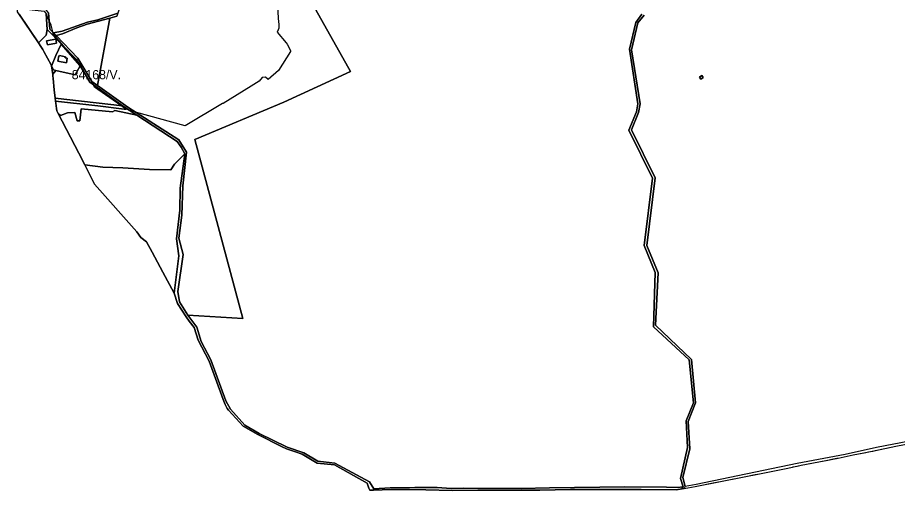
# Model space of a CAD drawing. Extents: x -477304 to -465429, y -1159113 to -1149210.
# Drawn here: x -472687 to -471252, y -1159113 to -1158342 of the extents above; entities that cross this region are included whole.
import ezdxf

# ---------------------------------------------------------------- set-up
doc = ezdxf.new("R2010")
doc.units = 0
for name, color, linetype in [('BPEJ_s', 7, 'Continuous'), ('ostatni_s', 7, 'Continuous'), ('PUPFL_s', 7, 'Continuous'), ('trav_porost_s', 7, 'Continuous')]:
    doc.layers.add(name, color=color, linetype=linetype)

msp = doc.modelspace()

# ---------------------------------------------------------------- linework, layer by layer
at = {"layer": 'BPEJ_s'}
msp.add_line((-472106.49, -1159112.88), (-472078.21, -1159112.05), dxfattribs=at)
for points in [[(-472265.73, -1158263.74), (-472261.91, -1158343.47), (-472260.85, -1158353.65), (-472260.85, -1158359.59), (-472262.02, -1158362.28), (-472263.61, -1158365.95), (-472248.55, -1158383.34), (-472247.32, -1158385.73), (-472241.98, -1158396.06), (-472241.98, -1158397.75), (-472261.06, -1158428.5), (-472278.24, -1158443.34), (-472282.69, -1158439.31), (-472287.99, -1158439.74), (-472292.66, -1158445.89), (-472305.8, -1158454.16), (-472351.6, -1158482.57), (-472352.45, -1158482.57), (-472413.61, -1158518.57), (-472494.46, -1158496.29), (-472500, -1158494.76), (-472504.44, -1158493.37), (-472510.2, -1158491.57), (-472518.4, -1158485.77), (-472561.24, -1158455.52), (-472563.55, -1158451.26), (-472571.49, -1158436.66), (-472576.43, -1158427.57), (-472578, -1158425.91), (-472588.26, -1158415.03), (-472600.95, -1158401.58), (-472612.08, -1158388.5), (-472628.9, -1158368.73), (-472629.67, -1158365.51), (-472632.33, -1158354.51), (-472635.42, -1158347.42), (-472640.28, -1158336.28)], [(-472265.73, -1158263.74), (-472261.91, -1158343.47), (-472260.85, -1158353.65), (-472260.85, -1158359.59), (-472262.02, -1158362.28), (-472263.61, -1158365.95), (-472248.55, -1158383.34), (-472247.32, -1158385.73), (-472241.98, -1158396.06), (-472241.98, -1158397.75), (-472261.06, -1158428.5), (-472278.24, -1158443.34), (-472282.69, -1158439.31), (-472287.99, -1158439.74), (-472292.66, -1158445.89), (-472305.8, -1158454.16), (-472351.6, -1158482.57), (-472352.45, -1158482.57), (-472413.61, -1158518.57), (-472494.46, -1158496.29), (-472500, -1158494.76), (-472504.44, -1158493.37), (-472510.2, -1158491.57), (-472513.19, -1158491.31), (-472555.96, -1158486.36), (-472624.87, -1158478.39), (-472624.88, -1158478.39), (-472622.97, -1158494.2), (-472620.8, -1158498.39), (-472587.24, -1158563.25), (-472577.32, -1158582.48), (-472561.25, -1158613.94), (-472492.21, -1158691.54), (-472485.63, -1158700.62), (-472476.75, -1158708.09), (-472467.3, -1158724.65), (-472450.08, -1158757.54), (-472431.32, -1158791.54), (-472426.3, -1158808.3), (-472411.66, -1158830.16), (-472406.77, -1158837.27), (-472398.9, -1158847.76), (-472392.31, -1158868.11), (-472374.4, -1158902.5), (-472351.69, -1158965.36)], [(-472684.26, -1158336.59), (-472652.61, -1158383.21), (-472648.83, -1158389.61), (-472646.9, -1158392.88), (-472645.98, -1158394.44), (-472644.14, -1158397.55), (-472632.14, -1158419.49), (-472631.64, -1158421.66), (-472631.1, -1158424.05), (-472630.04, -1158431.55), (-472629.64, -1158434.37), (-472629.25, -1158437.13), (-472628.6, -1158441.68), (-472627.33, -1158460.07), (-472625.47, -1158473.45), (-472624.88, -1158478.39), (-472624.87, -1158478.39), (-472555.96, -1158486.36), (-472513.19, -1158491.31), (-472510.2, -1158491.57), (-472518.4, -1158485.77), (-472561.24, -1158455.52), (-472563.55, -1158451.26), (-472571.49, -1158436.66), (-472576.43, -1158427.57), (-472578, -1158425.91), (-472588.26, -1158415.03), (-472600.95, -1158401.58), (-472612.08, -1158388.5), (-472628.9, -1158368.73), (-472629.67, -1158365.51), (-472632.33, -1158354.51), (-472635.42, -1158347.42), (-472640.28, -1158336.28)], [(-472351.69, -1158965.36), (-472348.41, -1158973.33), (-472345.03, -1158979.57), (-472342.98, -1158982.7), (-472319.03, -1159008.67), (-472295.2, -1159022.38), (-472255.57, -1159042.54), (-472248.04, -1159045.76), (-472234.94, -1159050.02), (-472222.67, -1159054.37), (-472198.26, -1159068.75), (-472170.01, -1159071.87), (-472116.62, -1159101.37), (-472114.01, -1159109.72), (-472112.58, -1159113.06), (-472106.49, -1159112.88)], [(-472078.21, -1159112.05), (-472047.81, -1159112.11), (-472021.14, -1159112.52), (-471977.91, -1159113.35), (-471936.22, -1159113.01), (-471890.93, -1159113.19), (-471834.93, -1159112.74), (-471785, -1159112.1), (-471763.77, -1159111.82), (-471752.7, -1159111.68), (-471734.12, -1159111.7), (-471689.5, -1159111.75), (-471689.33, -1159111.75), (-471689.22, -1159111.75), (-471688.14, -1159111.75), (-471685.96, -1159111.75), (-471680.14, -1159111.76), (-471669.78, -1159111.77), (-471669.68, -1159111.77), (-471660.21, -1159111.85), (-471645.72, -1159111.98), (-471611.89, -1159112.28), (-471603.14, -1159110.69), (-471602.61, -1159110.59), (-471599.77, -1159110.08), (-471599.35, -1159110), (-471581.37, -1159106.81), (-471549.7, -1159100.71), (-471543.64, -1159099.54), (-471540.41, -1159098.92), (-471493.61, -1159089.57), (-471489.04, -1159088.65), (-471484.02, -1159087.65), (-471476.57, -1159086.16), (-471474.07, -1159085.66), (-471433.45, -1159077.57), (-471422.79, -1159075.31), (-471421.78, -1159075.09), (-471415.52, -1159073.76), (-471408.77, -1159072.33), (-471371.33, -1159065.04), (-471367.83, -1159064.36), (-471365.45, -1159063.9), (-471358.66, -1159062.58), (-471350.7, -1159061.03), (-471348.39, -1159060.58), (-471323.83, -1159055.59), (-471306.74, -1159052.12), (-471305.92, -1159051.96), (-471299.03, -1159050.54), (-471292.08, -1159049.11), (-471287.45, -1159048.16), (-471254.45, -1159041.38), (-471240.01, -1159038.58)]]:
    msp.add_lwpolyline(points, dxfattribs=at)
at = {"layer": 'ostatni_s'}
for points in [[(-472636.66, -1158334.41), (-472634.14, -1158360.85), (-472628.35, -1158366.89), (-472623.97, -1158371.45), (-472588.71, -1158408.22), (-472565.63, -1158446.34), (-472556.65, -1158452.72), (-472506.92, -1158488.31), (-472423.92, -1158541.46), (-472411.56, -1158561.7), (-472417.57, -1158616.75), (-472418.95, -1158664.4), (-472423.83, -1158702.03), (-472417.07, -1158728.53), (-472425.73, -1158788.91), (-472422.84, -1158805.67), (-472408.96, -1158827.72), (-472394.58, -1158847.34), (-472387.53, -1158870.46), (-472371.56, -1158900.29), (-472347.13, -1158967.52), (-472339.75, -1158981), (-472316.38, -1159007.05), (-472293.04, -1159020.55), (-472247.08, -1159042.83), (-472220.16, -1159052.18), (-472197.25, -1159065.9), (-472169.29, -1159069.07), (-472112.77, -1159099.12), (-472105.93, -1159110.54), (-472106.49, -1159112.88), (-472112.58, -1159113.06), (-472114.01, -1159109.72), (-472116.62, -1159101.37), (-472170.01, -1159071.87), (-472198.26, -1159068.75), (-472222.67, -1159054.37), (-472234.94, -1159050.02), (-472248.04, -1159045.76), (-472255.57, -1159042.54), (-472295.2, -1159022.38), (-472319.03, -1159008.67), (-472342.98, -1158982.7), (-472345.03, -1158979.57), (-472348.41, -1158973.33), (-472351.69, -1158965.36), (-472374.4, -1158902.5), (-472392.31, -1158868.11), (-472398.9, -1158847.76), (-472406.77, -1158837.27), (-472411.66, -1158830.16), (-472426.3, -1158808.3), (-472431.32, -1158791.54), (-472423.99, -1158730.94), (-472427.41, -1158702.9), (-472422.13, -1158656.11), (-472421.5, -1158620.63), (-472414.06, -1158564.21), (-472420.02, -1158553.6), (-472426.34, -1158544.46), (-472492.55, -1158501.15), (-472515.55, -1158486.1), (-472568.9, -1158447.38), (-472584.99, -1158420.74), (-472591.13, -1158410.03), (-472638.44, -1158361.41), (-472640.4, -1158335.93)], [(-471664.69, -1158338.46), (-471674.96, -1158350.8), (-471685.46, -1158394.82), (-471671.6, -1158482.85), (-471674, -1158497.16), (-471685.4, -1158525.11), (-471646.64, -1158603.72), (-471660.68, -1158713.93), (-471642.02, -1158758.33), (-471646.5, -1158844.06), (-471587.57, -1158899.63), (-471581.07, -1158970.7), (-471592.91, -1159000.77), (-471590.23, -1159045.68), (-471601.85, -1159092.38), (-471597.73, -1159106.93), (-471599.35, -1159110), (-471599.77, -1159110.08), (-471603.14, -1159110.69), (-471601.46, -1159107.66), (-471605.7, -1159094.13), (-471594.34, -1159043.47), (-471596.58, -1158999.97), (-471584.35, -1158970.72), (-471591.37, -1158900.67), (-471649.86, -1158846.71), (-471646.64, -1158757.71), (-471664.56, -1158713.76), (-471651.3, -1158604.1), (-471689.68, -1158525.87), (-471677.39, -1158495.91), (-471675.29, -1158482.93), (-471688.96, -1158393.86), (-471678.55, -1158349.99), (-471668.72, -1158336.66)]]:
    msp.add_lwpolyline(points, dxfattribs=at)
for points in [[(-472573.2, -1158353.08), (-472590.17, -1158359.02), (-472613.81, -1158368.63), (-472623.97, -1158371.45), (-472628.35, -1158366.89), (-472614.22, -1158364.11), (-472572.65, -1158349.62), (-472555.93, -1158345.78), (-472523.33, -1158335.05), (-472524.97, -1158339.98), (-472536.51, -1158343.14)], [(-472638.44, -1158361.41), (-472591.13, -1158410.03), (-472584.99, -1158420.74), (-472615.9, -1158385.42), (-472624.62, -1158404.27), (-472631.64, -1158421.66), (-472632.14, -1158419.49), (-472644.14, -1158397.55), (-472645.98, -1158394.44), (-472646.9, -1158392.88), (-472648.83, -1158389.61), (-472652.61, -1158383.21), (-472640.26, -1158370.82)], [(-472639.52, -1158380.11), (-472624.5, -1158377.44), (-472623.3, -1158384.2), (-472638.31, -1158386.88)], [(-472624.5, -1158377.44), (-472639.52, -1158380.11), (-472638.31, -1158386.88), (-472623.3, -1158384.2)], [(-472631.64, -1158421.66), (-472624.62, -1158404.27), (-472615.9, -1158385.42), (-472584.99, -1158420.74), (-472592.7, -1158435.67), (-472624.52, -1158428.27), (-472628.21, -1158427.41)], [(-472618.49, -1158404.07), (-472608.78, -1158406), (-472609.15, -1158407.88), (-472605.83, -1158408.54), (-472607.32, -1158416.05), (-472621.34, -1158413.26), (-472619.67, -1158404.86), (-472618.68, -1158405.05)], [(-472621.34, -1158413.26), (-472607.32, -1158416.05), (-472605.83, -1158408.54), (-472609.15, -1158407.88), (-472608.78, -1158406), (-472618.49, -1158404.07), (-472618.68, -1158405.05), (-472619.67, -1158404.86)]]:
    msp.add_lwpolyline(points, close=True, dxfattribs=at)
at = {"layer": 'PUPFL_s'}
for points in [[(-472268.96, -1158207.08), (-472143.72, -1158430.34), (-472252.41, -1158479.89), (-472397.54, -1158541.15), (-472319.34, -1158833.04), (-472408.96, -1158827.72), (-472422.84, -1158805.67), (-472425.73, -1158788.91), (-472417.07, -1158728.53), (-472423.83, -1158702.03), (-472418.95, -1158664.4), (-472417.57, -1158616.75), (-472411.56, -1158561.7), (-472423.92, -1158541.46), (-472506.92, -1158488.31), (-472556.65, -1158452.72), (-472536.51, -1158343.14), (-472524.97, -1158339.98)], [(-471668.72, -1158336.66), (-471678.55, -1158349.99), (-471688.96, -1158393.86), (-471675.29, -1158482.93), (-471677.39, -1158495.91), (-471689.68, -1158525.87), (-471651.3, -1158604.1), (-471664.56, -1158713.76), (-471646.64, -1158757.71), (-471649.86, -1158846.71), (-471591.37, -1158900.67), (-471584.35, -1158970.72), (-471596.58, -1158999.97), (-471594.34, -1159043.47), (-471605.7, -1159094.13), (-471601.46, -1159107.66), (-471610.23, -1159108.88), (-471628.62, -1159108.22), (-471696.61, -1159107.72), (-471819.46, -1159109.01), (-471865.19, -1159109.99), (-471960.26, -1159109.52), (-471979.89, -1159110.29), (-472002.59, -1159108.76), (-472039.03, -1159108.45), (-472079.03, -1159109.18), (-472105.93, -1159110.54), (-472112.77, -1159099.12), (-472169.29, -1159069.07), (-472197.25, -1159065.9), (-472220.16, -1159052.18), (-472247.08, -1159042.83), (-472293.04, -1159020.55), (-472316.38, -1159007.05), (-472339.75, -1158981), (-472347.13, -1158967.52), (-472371.56, -1158900.29), (-472387.53, -1158870.46), (-472394.58, -1158847.34), (-472408.96, -1158827.72), (-472319.34, -1158833.04), (-472397.54, -1158541.15), (-472252.41, -1158479.89), (-472143.72, -1158430.34), (-472268.96, -1158207.08)], [(-471152.65, -1159017.86), (-471286.02, -1159043.61), (-471336.99, -1159054.97), (-471415.51, -1159069.52), (-471580.15, -1159103.82), (-471597.73, -1159106.93), (-471601.85, -1159092.38), (-471590.23, -1159045.68), (-471592.91, -1159000.77), (-471581.07, -1158970.7), (-471587.57, -1158899.63), (-471646.5, -1158844.06), (-471642.02, -1158758.33), (-471660.68, -1158713.93), (-471646.64, -1158603.72), (-471685.4, -1158525.11), (-471674, -1158497.16), (-471671.6, -1158482.85), (-471685.46, -1158394.82), (-471674.96, -1158350.8), (-471664.69, -1158338.46)], [(-471152.65, -1159017.86), (-471286.02, -1159043.61), (-471336.99, -1159054.97), (-471415.51, -1159069.52), (-471580.15, -1159103.82), (-471597.73, -1159106.93), (-471599.35, -1159110), (-471581.37, -1159106.81), (-471540.41, -1159098.92), (-471474.07, -1159085.66), (-471433.45, -1159077.57), (-471408.77, -1159072.33), (-471348.39, -1159060.58), (-471323.83, -1159055.59), (-471305.92, -1159051.96), (-471254.45, -1159041.38), (-471174.71, -1159025.92)]]:
    msp.add_lwpolyline(points, dxfattribs=at)
for points in [[(-472629.64, -1158434.37), (-472630.04, -1158431.55), (-472631.1, -1158424.05), (-472631.64, -1158421.66), (-472628.21, -1158427.41), (-472624.52, -1158428.27)], [(-472629.64, -1158434.37), (-472624.52, -1158428.27), (-472592.7, -1158435.67), (-472584.99, -1158420.74), (-472568.9, -1158447.38), (-472515.55, -1158486.1), (-472625.47, -1158473.45), (-472627.33, -1158460.07), (-472628.6, -1158441.68), (-472629.25, -1158437.13)], [(-471574.72, -1158439.55), (-471572.63, -1158442.73), (-471568.8, -1158440.17), (-471570.92, -1158436.89)], [(-471574.72, -1158439.55), (-471570.92, -1158436.89), (-471568.8, -1158440.17), (-471572.63, -1158442.73)], [(-472616.87, -1158501.77), (-472620.8, -1158498.39), (-472622.97, -1158494.2), (-472625.47, -1158473.45), (-472515.55, -1158486.1), (-472492.55, -1158501.15), (-472528.51, -1158493.78), (-472532.08, -1158495.97), (-472583.22, -1158491.09), (-472585.51, -1158510.53), (-472589.84, -1158510.42), (-472593.64, -1158497.02), (-472605.54, -1158497.77)], [(-472514.99, -1158587.14), (-472547.66, -1158585.95), (-472577.32, -1158582.48), (-472587.24, -1158563.25), (-472620.8, -1158498.39), (-472616.87, -1158501.77), (-472605.54, -1158497.77), (-472593.64, -1158497.02), (-472589.84, -1158510.42), (-472585.51, -1158510.53), (-472583.22, -1158491.09), (-472532.08, -1158495.97), (-472528.51, -1158493.78), (-472492.55, -1158501.15), (-472426.34, -1158544.46), (-472420.02, -1158553.6), (-472414.06, -1158564.21), (-472431.14, -1158581.45), (-472436.9, -1158590.48), (-472471.51, -1158590.13)], [(-472427.41, -1158702.9), (-472423.99, -1158730.94), (-472431.32, -1158791.54), (-472450.08, -1158757.54), (-472467.3, -1158724.65), (-472476.75, -1158708.09), (-472485.63, -1158700.62), (-472492.21, -1158691.54), (-472561.25, -1158613.94), (-472577.32, -1158582.48), (-472547.66, -1158585.95), (-472514.99, -1158587.14), (-472471.51, -1158590.13), (-472436.9, -1158590.48), (-472431.14, -1158581.45), (-472414.06, -1158564.21), (-472421.5, -1158620.63), (-472422.13, -1158656.11)], [(-472105.93, -1159110.54), (-472079.03, -1159109.18), (-472039.03, -1159108.45), (-472002.59, -1159108.76), (-471979.89, -1159110.29), (-471960.26, -1159109.52), (-471865.19, -1159109.99), (-471819.46, -1159109.01), (-471696.61, -1159107.72), (-471628.62, -1159108.22), (-471610.23, -1159108.88), (-471601.46, -1159107.66), (-471603.14, -1159110.69), (-471611.89, -1159112.28), (-471669.68, -1159111.77), (-471752.7, -1159111.68), (-471785, -1159112.1), (-471834.93, -1159112.74), (-471890.93, -1159113.19), (-471936.22, -1159113.01), (-471977.91, -1159113.35), (-472021.14, -1159112.52), (-472047.81, -1159112.11), (-472078.21, -1159112.05), (-472106.49, -1159112.88)]]:
    msp.add_lwpolyline(points, close=True, dxfattribs=at)
at = {"layer": 'trav_porost_s'}
for points in [[(-472500.19, -1158274.72), (-472503.36, -1158274.91), (-472523.33, -1158335.05), (-472555.93, -1158345.78), (-472572.65, -1158349.62), (-472614.22, -1158364.11), (-472628.35, -1158366.89), (-472634.14, -1158360.85), (-472636.66, -1158334.41), (-472643.25, -1158325.7), (-472649.52, -1158321.49), (-472663.62, -1158315.08), (-472605.89, -1158161.93), (-472513.48, -1158199.1), (-472501.26, -1158272.89), (-472500.21, -1158272.93)], [(-472640.4, -1158335.93), (-472638.44, -1158361.41), (-472640.26, -1158370.82), (-472652.61, -1158383.21), (-472686.81, -1158332.84), (-472686.88, -1158326.75), (-472643.77, -1158331.59)], [(-472565.63, -1158446.34), (-472588.71, -1158408.22), (-472623.97, -1158371.45), (-472613.81, -1158368.63), (-472590.17, -1158359.02), (-472573.2, -1158353.08), (-472536.51, -1158343.14), (-472556.65, -1158452.72)]]:
    msp.add_lwpolyline(points, close=True, dxfattribs=at)

# ---------------------------------------------------------------- texts
at = {"layer": 'BPEJ_s'}
msp.add_text('84168/V.', height=15, dxfattribs=at).set_placement((-472598.54, -1158442.78))

doc.saveas('drawing.dxf')
